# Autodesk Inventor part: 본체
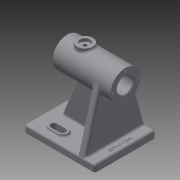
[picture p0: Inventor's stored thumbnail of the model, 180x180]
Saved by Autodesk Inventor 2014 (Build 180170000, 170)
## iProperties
Created: 2019-10
Part Number: 본체
Material: Generic
Document SubType Name: Modeling
Designer: kh
Density: 1 g/cm^3
Appearance: Default
Author: kh
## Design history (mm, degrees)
sketch "Sketch1"
  geometry: L1 (-50, 43)-(50, 43); L2 (50, 43)-(50, -43); L3 (50, -43)-(-50, -43); L4 (-50, -43)-(-50, 43); L5 (-50, 43)-(50, -43); L6 (50, 43)-(-50, -43); 1 further point
  constraints: 12 end point, 2 midpoint, 2 parallel, 1 horizontal, 1 perpendicular
  dimensions: "d0" = 100 distance of L1.start L1.end; "d1" = 86 distance of L1.end L2.end
extrude "Extrusion1" new body sketch "Sketch1" distance "d2" = 10; taper "d3" = 0 deg
sketch "Sketch2"
  geometry: L1 (-24, 27)-(-12, 27); L2 (-24, 34)-(-12, 34); L3 (-12, 20)-(-24, 20); L4 (-50, 43)-(-50, -43) reference; L5 (50, 43)-(-50, 43) reference; L6 (0, 0)-(-50, 0); L7 (-24, -27)-(-12, -27); L8 (-24, -34)-(-12, -34); L9 (-12, -20)-(-24, -20); A1 r 7 centre (-24, 27) between (-24, 34) and (-24, 20); A2 r 7 centre (-12, 27) between (-12, 20) and (-12, 34); A3 r 7 centre (-24, -27) between (-24, -20) and (-24, -34); A4 r 7 centre (-12, -27) between (-12, -34) and (-12, -20); 2 further points
  constraints: 18 end point, 8 point on circle, 7 symmetric about line, 4 centre point, 4 tangent, 2 midpoint, 1 horizontal, 1 parallel, 2 other
  dimensions: "d4" = 12 distance of L2.start L2.end; "d5" = 7 radius of A2; "d6" = 26 distance from line of L4 L2.start; "d7" = 16 distance from line of L5 point (-18, 27)
extrude "Extrusion2" join sketch "Sketch2" distance "d8" = 3; taper "d9" = 0 deg
sketch "Sketch3"
  geometry: L1 (32, 86)-(-50, 86); L2 (32, 86)-(32, 107); L3 (32, 107)-(-50, 107); L4 (-50, 107)-(-50, 86); L5 (32, 100.5)-(-30, 100.5); L6 (-30, 100.5)-(-30, 97.5); L7 (-30, 97.5)-(-50, 97.5); L8 (-50, 0)-(50, 0) reference; L9 (-50, 0)-(-50, 10) reference; 1 further point
  constraints: 14 end point, 4 perpendicular, 2 parallel, 2 point on line, 1 collinear, 1 horizontal
  dimensions: "d13" = 42 diameter of L3 L1; "d14" = 29 diameter of L5 L1; "d15" = 23 diameter of L7 L1; "d16" = 86 distance between parallel lines of L8 L1; "d17" = 82 distance of L2.end L3.end; "d18" = 62 distance between parallel lines of L2 L6
revolve "Revolution1" sketch "Sketch3" stored, may be unused: angle "d19" = 90 deg
workplane "Work Plane2"
  workplane "Work Plane1"
sketch "Sketch4"
  geometry: L1 (-41, 21)-(-41, -21) reference; L2 (-41, 0)-(30.519, 0); C1 r 11 at (-16, 0); 1 further point
  constraints: 2 end point, 1 centre point, 1 midpoint, 1 perpendicular, 1 point on line
  dimensions: "d21" = 22 diameter of C1; "d22" = 25 distance from line of L1 C1.centre
extrude "Extrusion3" join sketch "Sketch4" stored distance "d23" = 3; taper "d24" = 0 deg
hole "Hole1" diameter "d27" = 4.917; stored, may be unused: countersink angle "d31" = 90 deg, drill point angle "d33" = 0 deg; dims "d28" = 6, "d29" = 14, "d30" = 4, "d32" = 10, "d34" = 10, "d35" = 10
workplane "Work Plane3"
fillet "Fillet1" dims "d37" = 3
fillet "Fillet2" dims "d38" = 3
sketch "Sketch5"
  geometry: L1 (-42.896, 7.783)-(-20.272, 91.48); L2 (0, 0)-(0, 35.865); L3 (42.896, 7.783)-(20.272, 91.48); L4 (-40, 10)-(40, 10) reference; L5 (-42.896, 7.783)-(42.896, 7.783); A1 r 3 centre (-40, 7) between (-40, 10) and (-43, 7) reference; A2 r 3 centre (40, 7) between (43, 7) and (40, 10) reference; A3 r 21 centre (0, 86) between (-20.272, 91.48) and (20.272, 91.48); 1 further point
  constraints: 8 end point, 3 point on circle, 2 symmetric about line, 1 centre point, 1 coincident, 1 parallel, 1 tangent, 1 vertical, 4 other
extrude "Extrusion4" join sketch "Sketch5" distance "d39" = 10; taper "d40" = 0 deg
sketch "Sketch6"
  geometry: L1 (47, 10)-(-25, 10) reference; L2 (35, 10)-(18.524, 55.267); L3 (50, 0)-(50, 7) reference; 1 further point
  constraints: 2 end point, 1 point on line
  dimensions: "d41" = 15 distance from line of L3 L2.start; "d42" = 70 deg angle of L1 L2
feature "Rib1" sketch "Sketch6" dims "d43" = 1, "d44" = 10, "d45" = 0, "d46" = 0, "d47" = 1, "d48" = 1
sketch "Sketch7" dims "d49" = 36
  geometry: L1 (0, 0)-(-18, 0); C1 r 11.5 at (0, 0) reference; 2 further points
  constraints: 2 coincident, 2 end point, 1 horizontal, 1 horizontal alignment, 2 other
hole "Hole2" sketch "Sketch7" at (-18, 0) diameter "d50" = 2.459; stored, may be unused: countersink angle "d54" = 90 deg, drill point angle "d56" = 0 deg; dims "d51" = 8, "d52" = 14, "d53" = 4, "d55" = 10
pattern_circular "Circular Pattern1" dims angle "d58" = 360 deg
workplane "Work Plane4"
mirror "Mirror1"
workplane "Work Plane5"
sketch "Sketch8"
  geometry: L1 (40.598, -16.592)-(40.598, 16.592); L2 (40.598, 16.592)-(45.402, 16.592); L3 (45.402, 16.592)-(45.402, -16.592); L4 (45.402, -16.592)-(40.598, -16.592); L5 (45.402, -16.592)-(40.598, 16.592); L6 (-47, -43)-(47, -43) reference; L7 (50, -40)-(50, 40) reference; 2 further points
  constraints: 2 end point, 1 midpoint, 2 other
  dimensions: "d61" = 43 distance from line of L6 point (43, 0); "d62" = 7 distance from line of L7 point (43, 0)
emboss "Emboss1" sketch "Sketch8" dims "d0" = 100, "d1" = 86, "d4" = 12, "d5" = 7, "d6" = 26, "d7" = 16, "d63" = 0.5, "d64" = 0
sketch "Sketch9"
  geometry: L1 (-24, -27)-(-12, -27); L2 (-24, -31.5)-(-12, -31.5); L3 (-12, -22.5)-(-24, -22.5); L4 (0, 0)-(-26.131, 0); L5 (-24, 31.5)-(-12, 31.5); L6 (-12, 22.5)-(-24, 22.5); A1 r 7 centre (-24, -27) between (-24, -20) and (-24, -34) reference; A2 r 7 centre (-12, -27) between (-12, -34) and (-12, -20) reference; A3 r 4.5 centre (-24, -27) between (-24, -22.5) and (-24, -31.5); A4 r 4.5 centre (-12, -27) between (-12, -31.5) and (-12, -22.5); A5 r 4.5 centre (-12, 27) between (-12, 22.5) and (-12, 31.5); A6 r 4.5 centre (-24, 27) between (-24, 31.5) and (-24, 22.5); 1 further point
  constraints: 14 end point, 8 point on circle, 6 symmetric about line, 4 centre point, 4 tangent, 2 parallel, 1 horizontal, 1 midpoint, 2 other
  dimensions: "d65" = 4.5 radius of A4
extrude "Extrusion5" cut sketch "Sketch9" stored distance "d66" = 10; taper "d67" = 0 deg
fillet "Fillet3" dims "d68" = 3
chamfer "Chamfer1" distance "d69" = 1; stored, may be unused: second distance "d70" = 2, angle "d71" = 45 deg
fillet "Fillet4" dims "d72" = 3
fillet "Fillet5" dims "d73" = 3
fillet "Fillet6" dims "d74" = 3
fillet "Fillet7" dims "d75" = 3
body "Solid1"
other parameters: "d20" = 3, "d36" = 35, "d60" = 9.75
